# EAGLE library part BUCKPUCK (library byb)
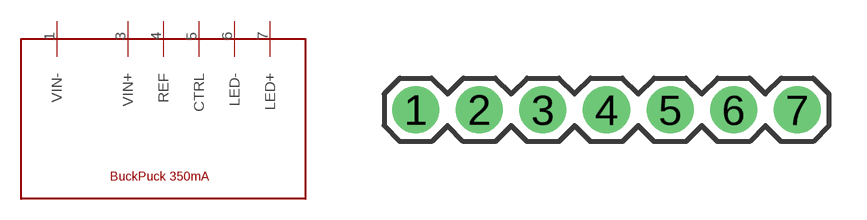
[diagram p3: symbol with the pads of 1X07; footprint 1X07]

Designator prefix -

## BUCKPUCK  [1X07]
1  VIN-
3  VIN+
4  REF
5  CTRL
6  LED-
7  LED+

## Footprint 1X07 (pad centres in mm)
drill 1.016 pad 1.88 round: 1 0,0; 2 2.54,0; 3 5.08,0; 4 7.62,0; 5 10.16,0; 6 12.7,0; 7 15.24,0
